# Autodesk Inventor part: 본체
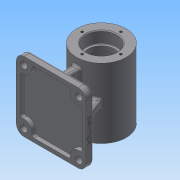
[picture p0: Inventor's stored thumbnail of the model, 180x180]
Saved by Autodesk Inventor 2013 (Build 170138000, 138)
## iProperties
Created: 2019-06
Part Number: 본체
Material: 일반
Document SubType Name: Modeling
Designer: Administrator
Density: 1 g/cm^3
Author: Administrator
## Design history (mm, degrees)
sketch "스케치1"
  geometry: L1 (32, 45)-(32, -45); L2 (32, -45)-(20, -45); L3 (20, -45)-(20, -30); L4 (20, -30)-(17, -30); L5 (17, -30)-(17, -24); L6 (17, -24)-(25, -24); L7 (25, -24)-(25, 24); L8 (25, 24)-(17, 24); L9 (17, 24)-(17, 30); L10 (17, 30)-(20, 30); L11 (20, 30)-(20, 45); L12 (20, 45)-(32, 45); L13 (0, 0)-(0, -14.682); 1 further point
  constraints: 26 end point, 6 parallel, 5 perpendicular, 1 collinear, 1 horizontal alignment, 1 midpoint, 1 vertical
  dimensions: "d0" = 90 distance of L1.start L1.end; "d2" = 64 diameter of L1 L13; "d3" = 50 diameter of L7 L13; "d4" = 40 diameter of L11 L13; "d5" = 34 diameter of L9 L13; "d6" = 15 distance between parallel lines of L10 L12; "d7" = 48 distance between parallel lines of L6 L8; "d8" = 15 distance between parallel lines of L2 L4; "d9" = 6 distance of L4.end L5.end; "d10" = 34 diameter of L5 L13; "d11" = 40 diameter of L3 L13
revolve "회전1" sketch "스케치1" stored, may be unused: angle "d12" = 90 deg
node "작업 평면1"
sketch "스케치2"
  geometry: L1 (45, 45)-(-45, 45); L2 (-45, 45)-(-45, -45); L3 (-45, -45)-(45, -45); L4 (45, -45)-(45, 45); L5 (45, 45)-(-45, -45); L6 (-45, 45)-(45, -45); 1 further point
  constraints: 12 end point, 2 midpoint, 2 parallel, 1 horizontal, 1 perpendicular
  dimensions: "d14" = 90 distance of L3.end L2.end; "d15" = 90 distance of L2.end L1.end
extrude "돌출1" join sketch "스케치2" distance "d16" = 10; taper "d17" = 0 deg
fillet "모깎기1" dims "d18" = 10
sketch "스케치3"
  geometry: L1 (5, -35)-(-5, -35); L2 (-5, -35)-(-5, 35); L3 (-5, 35)-(5, 35); L4 (5, 35)-(5, -35); L5 (5, -35)-(-5, 35); L6 (-5, -35)-(5, 35); 1 further point
  constraints: 12 end point, 2 midpoint, 2 parallel, 1 horizontal, 1 perpendicular
  dimensions: "d19" = 10 distance of L2.end L3.end; "d20" = 70 distance of L1.end L2.end
extrude "돌출2" join sketch "스케치3" stored distance "d21" = 0; taper "d22" = 0 deg
sketch "스케치4"
  geometry: L1 (-35, -55)-(-35, -65) reference; L2 (35, -55)-(-35, -55) reference; L3 (35, -65)-(35, -55) reference; L4 (35, -65)-(-35, -65) reference; L5 (-23.058, -22.189)-(-35, -55); L6 (-45, -65)-(-45, -55) reference; L7 (45, -55)-(45, -65) reference; L8 (-45, -55)-(-35, -55) reference; C1 r 20 at (0, 0) reference; 2 further points
  constraints: 2 end point, 1 point on line, 2 other
  dimensions: "d24" = 10 distance from line of L6 L5.end; "d78" = 110 deg angle of L8 L5
extrude "돌출3" join sketch "스케치4" stored distance "d28" = 10; taper "d29" = 0 deg
sketch "스케치5"
  geometry: C1 r 32 at (0, 0) reference; 1 further point
  constraints: 1 vertical alignment
  dimensions: "d30" = 25 distance of C1.centre point (0, 25)
hole "구멍1" sketch "스케치5" at (0, 25) diameter "d31" = 3.242; stored, may be unused: countersink angle "d35" = 90 deg, drill point angle "d37" = 118 deg; dims "d32" = 7, "d33" = 4, "d34" = 2, "d36" = 9
chamfer "모따기1" distance "d41" = 1; stored, may be unused: second distance "d42" = 2, angle "d43" = 45 deg
node "작업 평면2"
sketch "스케치6"
  geometry: C1 r 5 at (0, 0); 1 further point
  constraints: 1 centre point, 1 coincident
  dimensions: "d46" = 10 diameter of C1
extrude "돌출4" join sketch "스케치6" stored distance "d47" = 10; taper "d48" = 0 deg
hole "구멍2" diameter "d51" = 4.917; stored, may be unused: countersink angle "d55" = 90 deg, drill point angle "d57" = 118 deg; dims "d49" = 10, "d50" = 10, "d52" = 15, "d53" = 4, "d54" = 2, "d56" = 9
fillet "모깎기2" dims "d58" = 2, "d59" = 3, "d60" = 0.6
sketch "스케치7"
  geometry: L1 (-40, -40)-(40, -40); L2 (40, -40)-(40, 40); L3 (40, 40)-(-40, 40); L4 (-40, 40)-(-40, -40); L5 (-40, -40)-(40, 40); L6 (40, -40)-(-40, 40); 1 further point
  constraints: 12 end point, 2 midpoint, 2 parallel, 1 horizontal, 1 perpendicular
  dimensions: "d61" = 80 distance of L3.end L2.end; "d62" = 80 distance of L2.end L1.end
extrude "돌출5" cut sketch "스케치7" distance "d63" = 5; taper "d64" = 0 deg
sketch "스케치8"
  geometry: C1 r 10 at (-35, 35); C2 r 10 at (35, 35); C3 r 10 at (35, -35); C4 r 10 at (-35, -35); A1 r 10 centre (-35, 35) between (-35, 45) and (-45, 35) reference; A2 r 10 centre (35, 35) between (45, 35) and (35, 45) reference; A3 r 10 centre (35, -35) between (35, -45) and (45, -35) reference; A4 r 10 centre (-35, -35) between (-45, -35) and (-35, -45) reference; 1 further point
  constraints: 4 centre point, 4 coincident
  dimensions: "d65" = 20 diameter of C1; "d66" = 20 diameter of C2; "d67" = 20 diameter of C3; "d68" = 20 diameter of C4
extrude "돌출6" join sketch "스케치8" stored distance "d69" = 0; taper "d70" = 0 deg
fillet "모깎기3" dims "d71" = 3
sketch "스케치10"
  geometry: L1 (0, 0)-(70, 0) reference; L2 (-10, 7)-(-10, 0) reference; 2 further points
  constraints: 1 other
  dimensions: "d79" = 4 distance from line of point (35, 4) L1; "d80" = 45 distance from line of point (35, 4) L2
feature "엠보싱1" sketch "스케치10" dims "d14" = 90, "d15" = 90, "d81" = 0.5, "d82" = 0
sketch "스케치12"
  geometry: L1 (-45, 35)-(-45, -35) reference; L2 (35, 45)-(-35, 45) reference; C1 r 4.5 at (-35.5, 35.5); C2 r 4.5 at (35.5, 35.5); C3 r 4.5 at (35.5, -35.5); C4 r 4.5 at (-35.5, -35.5); 1 further point
  constraints: 4 centre point, 2 horizontal alignment, 2 vertical alignment
  dimensions: "d95" = 9 diameter of C1; "d96" = 9 diameter of C2; "d97" = 9 diameter of C3; "d98" = 9 diameter of C4; "d99" = 9.5 distance from line of L1 C1.centre; "d100" = 9.5 distance from line of C1.centre L2; "d101" = 80 dimension on C2 C1; "d102" = 80 dimension on C3 C2
extrude "돌출9" cut sketch "스케치12" distance "d103" = 10; taper "d104" = 0 deg
node "솔리드1"
mirror "대칭1"
pattern_circular "원형 패턴1" dims angle "d39" = 360 deg
mirror "대칭2"
node "투영된 루프1"
node "투영된 루프2"
other parameters: "d13" = -65
